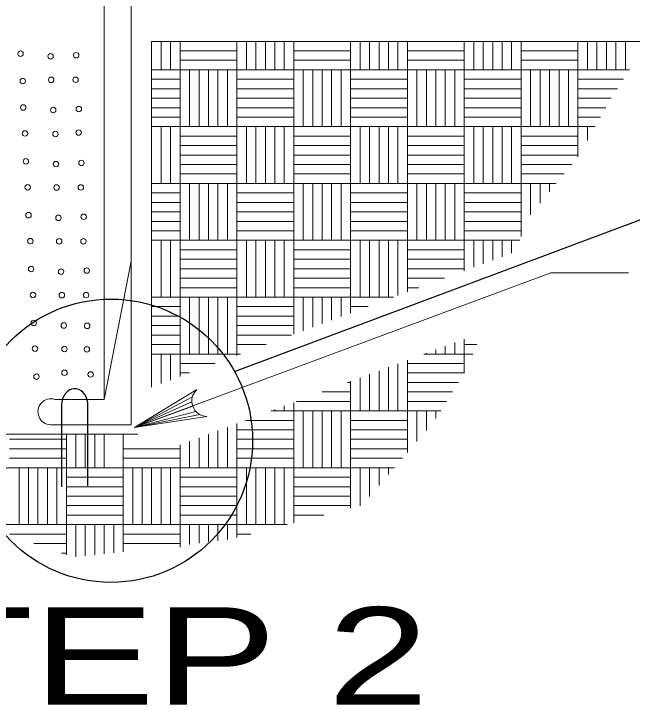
# Model space of a CAD drawing. Extents: x 1083.1 to 1117.1, y 719.4 to 741.4.
# Drawn here: x 1108.322 to 1109.844, y 733.245 to 734.949 of the extents above; entities that cross this region are included whole.
import ezdxf

# ---------------------------------------------------------------- set-up
doc = ezdxf.new("R2010")
doc.units = 0
doc.header["$LTSCALE"] = 0.062
doc.layers.add('1', color=7, linetype='Continuous', lineweight=13)

msp = doc.modelspace()

# ---------------------------------------------------------------- linework, layer by layer
at = {"layer": '1', "lineweight": 25}
for p, q in [((1108.8655, 734.06875), (1112.81717, 735.54867)), ((1108.43958, 733.98658), (1108.43958, 733.78558)), ((1108.50392, 733.78758), (1108.50392, 733.9915))]:
    msp.add_line(p, q, dxfattribs=at)
at = {"layer": '1'}
for p, q in [((1108.54417, 735.00583), (1108.54417, 734.0005)), ((1108.61133, 735.00583), (1108.61133, 733.93792)), ((1108.66133, 734.88167), (1111.2205, 734.88167)), ((1108.66133, 734.88167), (1108.66133, 734.03067)), ((1108.68467, 734.81167), (1108.68467, 734.88167)), ((1108.708, 734.81167), (1108.708, 734.88167)), ((1108.73133, 734.88167), (1108.87125, 734.88167)), ((1108.73133, 734.05667), (1108.73133, 734.88167)), ((1108.87125, 734.10875), (1108.87125, 734.88167)), ((1108.89458, 734.81167), (1108.89458, 734.88167)), ((1108.91792, 734.81167), (1108.91792, 734.88167)), ((1108.94125, 734.81167), (1108.94125, 734.88167)), ((1108.96458, 734.81167), (1108.96458, 734.88167)), ((1108.98792, 734.81167), (1108.98792, 734.88167)), ((1109.01117, 734.88167), (1109.15117, 734.88167)), ((1109.01117, 734.16075), (1109.01117, 734.88167)), ((1109.15117, 734.21275), (1109.15117, 734.88167)), ((1109.17442, 734.81167), (1109.17442, 734.88167)), ((1109.19775, 734.81167), (1109.19775, 734.88167)), ((1109.22108, 734.81167), (1109.22108, 734.88167)), ((1109.24442, 734.81167), (1109.24442, 734.88167)), ((1109.26775, 734.81167), (1109.26775, 734.88167)), ((1109.29108, 734.88167), (1109.431, 734.88167)), ((1109.29108, 734.26475), (1109.29108, 734.88167)), ((1109.431, 734.31683), (1109.431, 734.88167)), ((1109.45433, 734.81167), (1109.45433, 734.88167)), ((1109.47767, 734.81167), (1109.47767, 734.88167)), ((1109.501, 734.81167), (1109.501, 734.88167)), ((1109.52425, 734.81167), (1109.52425, 734.88167)), ((1109.54758, 734.81167), (1109.54758, 734.88167)), ((1109.57092, 734.40175), (1109.57092, 734.88167)), ((1109.57092, 734.88167), (1109.71083, 734.88167)), ((1109.71083, 734.59708), (1109.71083, 734.88167)), ((1109.73417, 734.81167), (1109.73417, 734.88167)), ((1109.7575, 734.81167), (1109.7575, 734.88167)), ((1109.78083, 734.81167), (1109.78083, 734.88167)), ((1109.80417, 734.81167), (1109.80417, 734.88167)), ((1109.8275, 734.81167), (1109.8275, 734.88167)), ((1108.73133, 734.85833), (1108.87125, 734.85833)), ((1109.01117, 734.85833), (1109.15117, 734.85833)), ((1109.29108, 734.85833), (1109.431, 734.85833)), ((1109.57092, 734.85833), (1109.71083, 734.85833)), ((1108.73133, 734.835), (1108.87125, 734.835)), ((1109.01117, 734.835), (1109.15117, 734.835)), ((1109.29108, 734.835), (1109.431, 734.835)), ((1109.57092, 734.835), (1109.71083, 734.835)), ((1108.66133, 734.81167), (1109.83775, 734.81167)), ((1108.75467, 734.67175), (1108.75467, 734.81167)), ((1108.778, 734.67175), (1108.778, 734.81167)), ((1108.80133, 734.67175), (1108.80133, 734.81167)), ((1108.82458, 734.67175), (1108.82458, 734.81167)), ((1108.84792, 734.67175), (1108.84792, 734.81167)), ((1109.0345, 734.67175), (1109.0345, 734.81167)), ((1109.05783, 734.67175), (1109.05783, 734.81167)), ((1109.08117, 734.67175), (1109.08117, 734.81167)), ((1109.1045, 734.67175), (1109.1045, 734.81167)), ((1109.12783, 734.67175), (1109.12783, 734.81167)), ((1109.31442, 734.67175), (1109.31442, 734.81167)), ((1109.33775, 734.67175), (1109.33775, 734.81167)), ((1109.361, 734.67175), (1109.361, 734.81167)), ((1109.38433, 734.67175), (1109.38433, 734.81167)), ((1109.40767, 734.67175), (1109.40767, 734.81167)), ((1109.59425, 734.67175), (1109.59425, 734.81167)), ((1109.61758, 734.67175), (1109.61758, 734.81167)), ((1109.64092, 734.67175), (1109.64092, 734.81167)), ((1109.66425, 734.67175), (1109.66425, 734.81167)), ((1109.68758, 734.67175), (1109.68758, 734.81167)), ((1108.66133, 734.78833), (1108.73133, 734.78833)), ((1108.87125, 734.78833), (1108.94125, 734.78833)), ((1108.94125, 734.78833), (1109.01117, 734.78833)), ((1109.15117, 734.78833), (1109.22108, 734.78833)), ((1109.22108, 734.78833), (1109.29108, 734.78833)), ((1109.431, 734.78833), (1109.501, 734.78833)), ((1109.501, 734.78833), (1109.57092, 734.78833)), ((1109.71083, 734.78833), (1109.78083, 734.78833)), ((1109.78083, 734.78833), (1109.82283, 734.78833)), ((1108.66133, 734.76508), (1108.73133, 734.76508)), ((1108.87125, 734.76508), (1108.94125, 734.76508)), ((1108.94125, 734.76508), (1109.01117, 734.76508)), ((1109.15117, 734.76508), (1109.22108, 734.76508)), ((1109.22108, 734.76508), (1109.29108, 734.76508)), ((1109.431, 734.76508), (1109.501, 734.76508)), ((1109.501, 734.76508), (1109.57092, 734.76508)), ((1109.71083, 734.76508), (1109.78083, 734.76508)), ((1109.78083, 734.76508), (1109.80783, 734.76508)), ((1108.66133, 734.74175), (1108.73133, 734.74175)), ((1108.87125, 734.74175), (1108.94125, 734.74175)), ((1108.94125, 734.74175), (1109.01117, 734.74175)), ((1109.15117, 734.74175), (1109.22108, 734.74175)), ((1109.22108, 734.74175), (1109.29108, 734.74175)), ((1109.431, 734.74175), (1109.501, 734.74175)), ((1109.501, 734.74175), (1109.57092, 734.74175)), ((1109.71083, 734.74175), (1109.78083, 734.74175)), ((1109.78083, 734.74175), (1109.79283, 734.74175)), ((1108.66133, 734.71842), (1108.73133, 734.71842)), ((1108.87125, 734.71842), (1108.94125, 734.71842)), ((1108.94125, 734.71842), (1109.01117, 734.71842)), ((1109.15117, 734.71842), (1109.22108, 734.71842)), ((1109.22108, 734.71842), (1109.29108, 734.71842)), ((1109.431, 734.71842), (1109.501, 734.71842)), ((1109.501, 734.71842), (1109.57092, 734.71842)), ((1109.71083, 734.71842), (1109.77942, 734.71842)), ((1108.66133, 734.69508), (1108.73133, 734.69508)), ((1108.87125, 734.69508), (1108.94125, 734.69508)), ((1108.94125, 734.69508), (1109.01117, 734.69508)), ((1109.15117, 734.69508), (1109.22108, 734.69508)), ((1109.22108, 734.69508), (1109.29108, 734.69508)), ((1109.431, 734.69508), (1109.501, 734.69508)), ((1109.501, 734.69508), (1109.57092, 734.69508)), ((1109.71083, 734.69508), (1109.76633, 734.69508)), ((1108.66133, 734.67175), (1109.75333, 734.67175)), ((1108.68467, 734.60183), (1108.68467, 734.67175)), ((1108.708, 734.60183), (1108.708, 734.67175)), ((1108.89458, 734.60183), (1108.89458, 734.67175)), ((1108.91792, 734.60183), (1108.91792, 734.67175)), ((1108.94125, 734.60183), (1108.94125, 734.67175)), ((1108.96458, 734.60183), (1108.96458, 734.67175)), ((1108.98792, 734.60183), (1108.98792, 734.67175)), ((1109.17442, 734.60183), (1109.17442, 734.67175)), ((1109.19775, 734.60183), (1109.19775, 734.67175)), ((1109.22108, 734.60183), (1109.22108, 734.67175)), ((1109.24442, 734.60183), (1109.24442, 734.67175)), ((1109.26775, 734.60183), (1109.26775, 734.67175)), ((1109.45433, 734.60183), (1109.45433, 734.67175)), ((1109.47767, 734.60183), (1109.47767, 734.67175)), ((1109.501, 734.60183), (1109.501, 734.67175)), ((1109.52425, 734.60183), (1109.52425, 734.67175)), ((1109.54758, 734.60183), (1109.54758, 734.67175)), ((1109.73417, 734.6375), (1109.73417, 734.67175)), ((1108.73133, 734.64842), (1108.87125, 734.64842)), ((1109.01117, 734.64842), (1109.15117, 734.64842)), ((1109.29108, 734.64842), (1109.431, 734.64842)), ((1109.57092, 734.64842), (1109.71083, 734.64842)), ((1108.73133, 734.62517), (1108.87125, 734.62517)), ((1109.01117, 734.62517), (1109.15117, 734.62517)), ((1109.29108, 734.62517), (1109.431, 734.62517)), ((1109.57092, 734.62517), (1109.71083, 734.62517)), ((1108.68467, 734.53183), (1108.68467, 734.60183)), ((1108.708, 734.53183), (1108.708, 734.60183)), ((1108.73133, 734.60183), (1108.87125, 734.60183)), ((1108.89458, 734.53183), (1108.89458, 734.60183)), ((1108.91792, 734.53183), (1108.91792, 734.60183)), ((1108.94125, 734.53183), (1108.94125, 734.60183)), ((1108.96458, 734.53183), (1108.96458, 734.60183)), ((1108.98792, 734.53183), (1108.98792, 734.60183)), ((1109.01117, 734.60183), (1109.15117, 734.60183)), ((1109.17442, 734.53183), (1109.17442, 734.60183)), ((1109.19775, 734.53183), (1109.19775, 734.60183)), ((1109.22108, 734.53183), (1109.22108, 734.60183)), ((1109.24442, 734.53183), (1109.24442, 734.60183)), ((1109.26775, 734.53183), (1109.26775, 734.60183)), ((1109.29108, 734.60183), (1109.431, 734.60183)), ((1109.45433, 734.53183), (1109.45433, 734.60183)), ((1109.47767, 734.53183), (1109.47767, 734.60183)), ((1109.501, 734.53183), (1109.501, 734.60183)), ((1109.52425, 734.53183), (1109.52425, 734.60183)), ((1109.54758, 734.53183), (1109.54758, 734.60183)), ((1109.57092, 734.60183), (1109.71083, 734.60183)), ((1108.73133, 734.5785), (1108.87125, 734.5785)), ((1109.01117, 734.5785), (1109.15117, 734.5785)), ((1109.29108, 734.5785), (1109.431, 734.5785)), ((1109.57092, 734.5785), (1109.69567, 734.5785)), ((1108.73133, 734.55517), (1108.87125, 734.55517)), ((1109.01117, 734.55517), (1109.15117, 734.55517)), ((1109.29108, 734.55517), (1109.431, 734.55517)), ((1109.57092, 734.55517), (1109.67658, 734.55517)), ((1108.66133, 734.53183), (1109.65742, 734.53183)), ((1108.75467, 734.39192), (1108.75467, 734.53183)), ((1108.778, 734.39192), (1108.778, 734.53183)), ((1108.80133, 734.39192), (1108.80133, 734.53183)), ((1108.82458, 734.39192), (1108.82458, 734.53183)), ((1108.84792, 734.39192), (1108.84792, 734.53183)), ((1109.0345, 734.39192), (1109.0345, 734.53183)), ((1109.05783, 734.39192), (1109.05783, 734.53183)), ((1109.08117, 734.39192), (1109.08117, 734.53183)), ((1109.1045, 734.39192), (1109.1045, 734.53183)), ((1109.12783, 734.39192), (1109.12783, 734.53183)), ((1109.31442, 734.39192), (1109.31442, 734.53183)), ((1109.33775, 734.39192), (1109.33775, 734.53183)), ((1109.361, 734.39192), (1109.361, 734.53183)), ((1109.38433, 734.39192), (1109.38433, 734.53183)), ((1109.40767, 734.39192), (1109.40767, 734.53183)), ((1109.59425, 734.45492), (1109.59425, 734.53183)), ((1109.61758, 734.48333), (1109.61758, 734.53183)), ((1109.64092, 734.51175), (1109.64092, 734.53183)), ((1108.66133, 734.5085), (1108.73133, 734.5085)), ((1108.87125, 734.5085), (1108.94125, 734.5085)), ((1108.94125, 734.5085), (1109.01117, 734.5085)), ((1109.15117, 734.5085), (1109.22108, 734.5085)), ((1109.22108, 734.5085), (1109.29108, 734.5085)), ((1109.431, 734.5085), (1109.501, 734.5085)), ((1109.501, 734.5085), (1109.57092, 734.5085)), ((1108.66133, 734.48525), (1108.73133, 734.48525)), ((1108.87125, 734.48525), (1108.94125, 734.48525)), ((1108.94125, 734.48525), (1109.01117, 734.48525)), ((1109.15117, 734.48525), (1109.22108, 734.48525)), ((1109.22108, 734.48525), (1109.29108, 734.48525)), ((1109.431, 734.48525), (1109.501, 734.48525)), ((1109.501, 734.48525), (1109.57092, 734.48525)), ((1108.66133, 734.46192), (1108.73133, 734.46192)), ((1108.87125, 734.46192), (1108.94125, 734.46192)), ((1108.94125, 734.46192), (1109.01117, 734.46192)), ((1109.15117, 734.46192), (1109.22108, 734.46192)), ((1109.22108, 734.46192), (1109.29108, 734.46192)), ((1109.431, 734.46192), (1109.501, 734.46192)), ((1109.501, 734.46192), (1109.57092, 734.46192)), ((1108.66133, 734.43858), (1108.73133, 734.43858)), ((1108.87125, 734.43858), (1108.94125, 734.43858)), ((1108.94125, 734.43858), (1109.01117, 734.43858)), ((1109.15117, 734.43858), (1109.22108, 734.43858)), ((1109.22108, 734.43858), (1109.29108, 734.43858)), ((1109.431, 734.43858), (1109.501, 734.43858)), ((1109.501, 734.43858), (1109.57092, 734.43858)), ((1108.66133, 734.41525), (1108.73133, 734.41525)), ((1108.87125, 734.41525), (1108.94125, 734.41525)), ((1108.94125, 734.41525), (1109.01117, 734.41525)), ((1109.15117, 734.41525), (1109.22108, 734.41525)), ((1109.22108, 734.41525), (1109.29108, 734.41525)), ((1109.431, 734.41525), (1109.501, 734.41525)), ((1109.501, 734.41525), (1109.57092, 734.41525)), ((1108.66133, 734.39192), (1109.56742, 734.39192)), ((1108.68467, 734.322), (1108.68467, 734.39192)), ((1108.708, 734.322), (1108.708, 734.39192)), ((1108.89458, 734.322), (1108.89458, 734.39192)), ((1108.91792, 734.322), (1108.91792, 734.39192)), ((1108.94125, 734.322), (1108.94125, 734.39192)), ((1108.96458, 734.322), (1108.96458, 734.39192)), ((1108.98792, 734.322), (1108.98792, 734.39192)), ((1109.17442, 734.322), (1109.17442, 734.39192)), ((1109.19775, 734.322), (1109.19775, 734.39192)), ((1109.22108, 734.322), (1109.22108, 734.39192)), ((1109.24442, 734.322), (1109.24442, 734.39192)), ((1109.26775, 734.322), (1109.26775, 734.39192)), ((1109.45433, 734.3255), (1109.45433, 734.39192)), ((1109.47767, 734.33417), (1109.47767, 734.39192)), ((1109.501, 734.34283), (1109.501, 734.39192)), ((1109.52425, 734.3515), (1109.52425, 734.39192)), ((1109.54758, 734.36017), (1109.54758, 734.39192)), ((1108.73133, 734.36858), (1108.87125, 734.36858)), ((1109.01117, 734.36858), (1109.15117, 734.36858)), ((1109.29108, 734.36858), (1109.431, 734.36858)), ((1108.54417, 734.0005), (1108.61133, 734.34042)), ((1108.73133, 734.34525), (1108.87125, 734.34525)), ((1109.01117, 734.34525), (1109.15117, 734.34525)), ((1109.29108, 734.34525), (1109.431, 734.34525)), ((1108.68467, 734.252), (1108.68467, 734.322)), ((1108.708, 734.252), (1108.708, 734.322)), ((1108.73133, 734.322), (1108.87125, 734.322)), ((1108.89458, 734.252), (1108.89458, 734.322)), ((1108.91792, 734.252), (1108.91792, 734.322)), ((1108.94125, 734.252), (1108.94125, 734.322)), ((1108.96458, 734.252), (1108.96458, 734.322)), ((1108.98792, 734.252), (1108.98792, 734.322)), ((1109.01117, 734.322), (1109.15117, 734.322)), ((1109.17442, 734.252), (1109.17442, 734.322)), ((1109.19775, 734.252), (1109.19775, 734.322)), ((1109.22108, 734.252), (1109.22108, 734.322)), ((1109.24442, 734.252), (1109.24442, 734.322)), ((1109.26775, 734.25608), (1109.26775, 734.322)), ((1109.29108, 734.322), (1109.431, 734.322)), ((1108.73133, 734.29867), (1108.87125, 734.29867)), ((1109.01117, 734.29867), (1109.15117, 734.29867)), ((1109.29108, 734.29867), (1109.38217, 734.29867)), ((1108.73133, 734.27533), (1108.87125, 734.27533)), ((1109.01117, 734.27533), (1109.15117, 734.27533)), ((1109.29108, 734.27533), (1109.31942, 734.27533)), ((1108.66133, 734.252), (1109.25667, 734.252)), ((1108.75467, 734.11208), (1108.75467, 734.252)), ((1108.778, 734.11208), (1108.778, 734.252)), ((1108.80133, 734.11208), (1108.80133, 734.252)), ((1108.82458, 734.11208), (1108.82458, 734.252)), ((1108.84792, 734.11208), (1108.84792, 734.252)), ((1109.0345, 734.16942), (1109.0345, 734.252)), ((1109.05783, 734.17808), (1109.05783, 734.252)), ((1109.08117, 734.18675), (1109.08117, 734.252)), ((1109.1045, 734.19542), (1109.1045, 734.252)), ((1109.12783, 734.20408), (1109.12783, 734.252)), ((1108.66133, 734.22867), (1108.73133, 734.22867)), ((1108.87125, 734.22867), (1108.94125, 734.22867)), ((1108.94125, 734.22867), (1109.01117, 734.22867)), ((1109.15117, 734.22867), (1109.194, 734.22867)), ((1108.66133, 734.20533), (1108.73133, 734.20533)), ((1108.87125, 734.20533), (1108.94125, 734.20533)), ((1108.94125, 734.20533), (1109.01117, 734.20533)), ((1108.66133, 734.18208), (1108.73133, 734.18208)), ((1108.87125, 734.18208), (1108.94125, 734.18208)), ((1108.94125, 734.18208), (1109.01117, 734.18208)), ((1108.66133, 734.15875), (1108.73133, 734.15875)), ((1108.87125, 734.15875), (1108.94125, 734.15875)), ((1108.94125, 734.15875), (1109.00575, 734.15875)), ((1108.66133, 734.13542), (1108.73133, 734.13542)), ((1108.87125, 734.13542), (1108.94308, 734.13542)), ((1109.40767, 734.11208), (1109.40767, 734.14025)), ((1109.431, 734.06517), (1109.431, 734.149)), ((1109.431, 734.13542), (1109.4615, 734.13542)), ((1109.361, 734.11208), (1109.361, 734.12292)), ((1109.38433, 734.11208), (1109.38433, 734.13158)), ((1108.66133, 734.11208), (1108.88033, 734.11208)), ((1108.68467, 734.03933), (1108.68467, 734.11208)), ((1108.708, 734.048), (1108.708, 734.11208)), ((1109.33183, 734.11208), (1109.45192, 734.11208)), ((1109.33775, 734.11208), (1109.33775, 734.11425)), ((1108.73133, 734.08875), (1108.81758, 734.08875)), ((1109.26775, 733.97217), (1109.26775, 734.08825)), ((1109.29108, 733.86958), (1109.29108, 734.09692)), ((1109.29108, 734.08875), (1109.431, 734.08875)), ((1108.73133, 734.06542), (1108.75483, 734.06542)), ((1109.22108, 734.04217), (1109.22108, 734.07092)), ((1109.24442, 733.97217), (1109.24442, 734.07958)), ((1109.29108, 734.06542), (1109.431, 734.06542)), ((1109.17442, 733.97217), (1109.17442, 734.05358)), ((1109.19775, 733.97217), (1109.19775, 734.06225)), ((1109.14367, 734.04217), (1109.15117, 734.04217)), ((1109.15117, 733.99625), (1109.15117, 734.04492)), ((1109.22108, 733.97217), (1109.22108, 734.04217)), ((1109.24442, 734.03983), (1109.24442, 734.04217)), ((1109.29108, 734.04217), (1109.41658, 734.04217)), ((1109.08092, 734.01883), (1109.15117, 734.01883)), ((1109.29108, 734.01883), (1109.40208, 734.01883)), ((1108.54417, 734.0005), (1108.42333, 734.0005)), ((1108.76167, 734.00692), (1108.61883, 733.93092)), ((1108.76033, 733.99467), (1108.61883, 733.93092)), ((1108.76267, 733.98342), (1108.61883, 733.93092)), ((1108.98792, 733.97217), (1108.98792, 733.98425)), ((1109.01117, 733.87683), (1109.01117, 733.99292)), ((1109.01817, 733.9955), (1109.15117, 733.9955)), ((1109.15117, 733.73283), (1109.15117, 733.99592)), ((1109.29108, 733.9955), (1109.3875, 733.9955)), ((1108.77025, 733.97092), (1108.61883, 733.93092)), ((1108.77958, 733.96325), (1108.61883, 733.93092)), ((1108.95542, 733.97217), (1109.28717, 733.97217)), ((1108.96458, 733.97217), (1108.96458, 733.97558)), ((1109.0345, 733.95058), (1109.0345, 733.97217)), ((1109.0345, 733.83225), (1109.0345, 733.97217)), ((1109.05783, 733.95817), (1109.05783, 733.97217)), ((1109.05783, 733.83225), (1109.05783, 733.97217)), ((1109.08117, 733.96575), (1109.08117, 733.97217)), ((1109.08117, 733.83225), (1109.08117, 733.97217)), ((1109.1045, 733.83225), (1109.1045, 733.97217)), ((1109.12783, 733.83225), (1109.12783, 733.97217)), ((1109.28808, 733.97217), (1109.37292, 733.97217)), ((1109.31442, 733.89658), (1109.31442, 733.97217)), ((1109.33775, 733.9235), (1109.33775, 733.97217)), ((1109.361, 733.95308), (1109.361, 733.97217)), ((1108.89275, 733.94883), (1108.94125, 733.94883)), ((1108.94125, 733.94883), (1109.01117, 733.94883)), ((1109.15117, 733.94883), (1109.29108, 733.94883)), ((1108.61133, 733.93792), (1108.41267, 733.93792)), ((1108.84792, 733.83225), (1108.84792, 733.93217)), ((1108.87125, 733.66017), (1108.87125, 733.94083)), ((1108.4515, 733.61825), (1108.4515, 733.915)), ((1108.47475, 733.83225), (1108.47475, 733.915)), ((1108.49808, 733.83225), (1108.49808, 733.915)), ((1108.52142, 733.83225), (1108.52142, 733.915)), ((1108.54475, 733.83225), (1108.54475, 733.915)), ((1108.59142, 733.62533), (1108.59142, 733.915)), ((1108.59142, 733.912), (1108.59142, 733.915)), ((1108.80133, 733.83225), (1108.80133, 733.91483)), ((1108.82458, 733.83225), (1108.82458, 733.9235)), ((1108.87125, 733.9255), (1109.01117, 733.9255)), ((1109.15117, 733.9255), (1109.22108, 733.9255)), ((1109.22108, 733.9255), (1109.29108, 733.9255)), ((1108.3115, 733.90225), (1108.3815, 733.90225)), ((1108.3815, 733.90225), (1108.4515, 733.90225)), ((1108.75467, 733.83225), (1108.75467, 733.8975)), ((1108.778, 733.83225), (1108.778, 733.90617)), ((1108.87125, 733.90225), (1109.01117, 733.90225)), ((1109.15117, 733.90225), (1109.22108, 733.90225)), ((1109.22108, 733.90225), (1109.29108, 733.90225)), ((1108.3115, 733.87892), (1108.3815, 733.87892)), ((1108.3815, 733.87892), (1108.4515, 733.87892)), ((1108.591, 733.87892), (1108.73133, 733.87892)), ((1108.73133, 733.63692), (1108.73133, 733.88883)), ((1108.87075, 733.87892), (1109.01117, 733.87892)), ((1109.01117, 733.6965), (1109.01117, 733.87875)), ((1109.15117, 733.87892), (1109.22108, 733.87892)), ((1109.22108, 733.87892), (1109.29108, 733.87892)), ((1108.3115, 733.85558), (1108.3815, 733.85558)), ((1108.3815, 733.85558), (1108.4515, 733.85558)), ((1108.59283, 733.85558), (1108.73133, 733.85558)), ((1108.87075, 733.85558), (1108.94125, 733.85558)), ((1108.94125, 733.85558), (1109.01117, 733.85558)), ((1109.15117, 733.85558), (1109.22108, 733.85558)), ((1109.22108, 733.85558), (1109.279, 733.85558)), ((1107.62867, 733.83225), (1108.61858, 733.83225)), ((1108.33483, 733.76233), (1108.33483, 733.83225)), ((1108.35817, 733.76233), (1108.35817, 733.83225)), ((1108.3815, 733.76233), (1108.3815, 733.83225)), ((1108.40483, 733.76233), (1108.40483, 733.83225)), ((1108.42817, 733.76233), (1108.42817, 733.83225)), ((1108.61475, 733.76233), (1108.61475, 733.83225)), ((1108.61858, 733.83225), (1109.25883, 733.83225)), ((1108.63808, 733.76233), (1108.63808, 733.83225)), ((1108.66133, 733.76233), (1108.66133, 733.83225)), ((1108.68467, 733.76233), (1108.68467, 733.83225)), ((1108.708, 733.76233), (1108.708, 733.83225)), ((1108.89458, 733.76233), (1108.89458, 733.83225)), ((1108.91792, 733.76233), (1108.91792, 733.83225)), ((1108.94125, 733.76233), (1108.94125, 733.83225)), ((1108.96458, 733.76233), (1108.96458, 733.83225)), ((1108.98792, 733.76233), (1108.98792, 733.83225)), ((1109.17442, 733.76233), (1109.17442, 733.83225)), ((1109.19775, 733.76233), (1109.19775, 733.83225)), ((1109.22108, 733.7885), (1109.22108, 733.83225)), ((1109.24442, 733.8155), (1109.24442, 733.83225)), ((1108.4515, 733.80892), (1108.59142, 733.80892)), ((1108.73133, 733.80892), (1108.87125, 733.80892)), ((1109.01117, 733.80892), (1109.15117, 733.80892)), ((1108.4515, 733.78558), (1108.59142, 733.78558)), ((1108.73133, 733.78558), (1108.87125, 733.78558)), ((1109.01117, 733.78558), (1109.15117, 733.78558)), ((1108.33483, 733.69233), (1108.33483, 733.76233)), ((1108.35817, 733.69233), (1108.35817, 733.76233)), ((1108.3815, 733.69233), (1108.3815, 733.76233)), ((1108.40483, 733.69233), (1108.40483, 733.76233)), ((1108.42817, 733.69233), (1108.42817, 733.76233)), ((1108.4515, 733.76233), (1108.59142, 733.76233)), ((1108.61475, 733.69233), (1108.61475, 733.76233)), ((1108.63808, 733.69233), (1108.63808, 733.76233)), ((1108.66133, 733.69233), (1108.66133, 733.76233)), ((1108.68467, 733.69233), (1108.68467, 733.76233)), ((1108.708, 733.69233), (1108.708, 733.76233)), ((1108.73133, 733.76233), (1108.87125, 733.76233)), ((1108.89458, 733.69233), (1108.89458, 733.76233)), ((1108.91792, 733.69233), (1108.91792, 733.76233)), ((1108.94125, 733.69233), (1108.94125, 733.76233)), ((1108.96458, 733.69233), (1108.96458, 733.76233)), ((1108.98792, 733.69233), (1108.98792, 733.76233)), ((1109.01117, 733.76233), (1109.15117, 733.76233)), ((1109.17442, 733.73883), (1109.17442, 733.76233)), ((1109.19775, 733.76158), (1109.19775, 733.76233)), ((1108.4515, 733.739), (1108.59142, 733.739)), ((1108.73133, 733.739), (1108.87125, 733.739)), ((1109.01117, 733.739), (1109.15117, 733.739)), ((1108.4515, 733.71567), (1108.59142, 733.71567)), ((1108.73133, 733.71567), (1108.87125, 733.71567)), ((1109.01117, 733.71567), (1109.08508, 733.71567)), ((1107.87517, 733.69233), (1108.61858, 733.69233)), ((1108.47475, 733.61267), (1108.47475, 733.69233)), ((1108.49808, 733.61517), (1108.49808, 733.69233)), ((1108.52142, 733.61775), (1108.52142, 733.69233)), ((1108.54475, 733.62025), (1108.54475, 733.69233)), ((1108.56808, 733.62275), (1108.56808, 733.69233)), ((1108.61858, 733.69233), (1108.99508, 733.69233)), ((1108.75467, 733.64358), (1108.75467, 733.69233)), ((1108.778, 733.64658), (1108.778, 733.69233)), ((1108.80133, 733.64967), (1108.80133, 733.69233)), ((1108.82458, 733.65267), (1108.82458, 733.69233)), ((1108.84792, 733.65575), (1108.84792, 733.69233)), ((1108.3115, 733.669), (1108.3815, 733.669)), ((1108.3815, 733.669), (1108.4515, 733.669)), ((1108.59142, 733.669), (1108.61858, 733.669)), ((1108.61858, 733.669), (1108.66133, 733.669)), ((1108.66133, 733.669), (1108.73133, 733.669)), ((1108.87125, 733.669), (1108.90517, 733.669)), ((1108.37133, 733.64567), (1108.3815, 733.64567)), ((1108.3815, 733.64567), (1108.4515, 733.64567)), ((1108.59142, 733.64567), (1108.61858, 733.64567)), ((1108.61858, 733.64567), (1108.66133, 733.64567)), ((1108.66133, 733.64567), (1108.73133, 733.64567)), ((1108.43942, 733.62233), (1108.4515, 733.62233))]:
    msp.add_line(p, q, dxfattribs=at)
for points in [[(1108.61883, 733.93092), (1109.644, 734.31208), (1109.83517, 734.31208)], [(1108.79725, 733.95833), (1108.61883, 733.93092), (1108.77292, 734.02483)], [(1108.62708, 733.915), (1108.61858, 733.915), (1108.26033, 733.915)]]:
    msp.add_lwpolyline(points, dxfattribs=at)
at = {"layer": '1', "lineweight": 25}
msp.add_circle((1108.56107, 733.8987), 0.34868, dxfattribs=at)
at = {"layer": '1'}
for centre, radius, start, end in [((1108.7985, 733.99654), 0.0382, 132.12971, 267.95584), ((1108.4136, 733.96996), 0.03206, 72.32209, 268.34559)]:
    msp.add_arc(centre, radius, start, end, dxfattribs=at)
for centre in [(1108.33868, 734.85133), (1108.41248, 734.84484), (1108.47562, 734.84758), (1108.34418, 734.78404), (1108.41423, 734.78695), (1108.47404, 734.78712), (1108.34518, 734.71882), (1108.41906, 734.71258), (1108.48212, 734.71508), (1108.34968, 734.65495), (1108.34968, 734.65495), (1108.48153, 734.65719), (1108.42448, 734.65361), (1108.35168, 734.58632), (1108.42589, 734.57949), (1108.48861, 734.58257), (1108.35618, 734.52244), (1108.42723, 734.52194), (1108.48703, 734.5221), (1108.35817, 734.45381), (1108.49386, 734.4499), (1108.43197, 734.44731), (1108.36267, 734.38993), (1108.43372, 734.38943), (1108.49353, 734.3896), (1108.36467, 734.3213), (1108.43847, 734.31481), (1108.50161, 734.31756), (1108.36917, 734.25742), (1108.44022, 734.25692), (1108.50002, 734.25709), (1108.37117, 734.1888), (1108.44497, 734.1823), (1108.50261, 734.18147), (1108.37425, 734.12533), (1108.44672, 734.12442), (1108.50202, 734.12375), (1108.44681, 734.066), (1108.51115, 734.06175), (1108.37767, 734.05629)]:
    msp.add_ellipse(centre, major_axis=(0.00673, 0), ratio=0.999895, dxfattribs=at)
at = {"layer": '1', "lineweight": 25}
msp.add_ellipse((1108.47188, 733.9858), major_axis=(0.00099, 0.04097), ratio=0.78812, start_param=4.8785287, end_param=7.8539922, dxfattribs=at)

# ---------------------------------------------------------------- texts
at = {"layer": '1', "width": 1.4}
msp.add_text('STEP 2', height=0.24, dxfattribs=at).set_placement((1107.7955, 733.24883))

doc.saveas('drawing.dxf')
